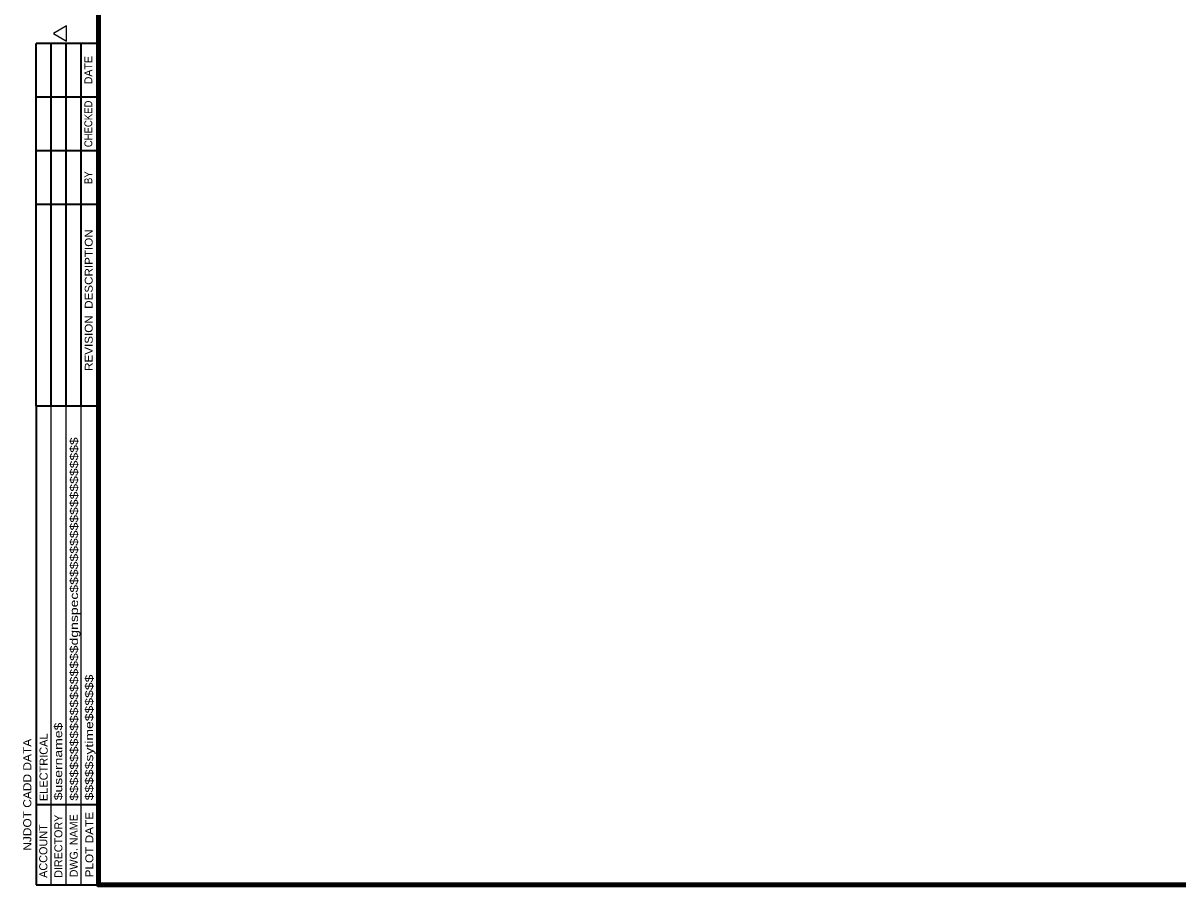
# Model space of a CAD drawing. Extents: x 168203 to 169864, y 223196 to 223870.
# Drawn here: x 169121.7 to 169229.9, y 223368.6 to 223449.3 of the extents above; entities that cross this region are included whole.
import ezdxf
from ezdxf.enums import TextEntityAlignment as Align

# ---------------------------------------------------------------- set-up
doc = ezdxf.new("R2010")
doc.units = 0
doc.header["$LTSCALE"] = 0.3
doc.layers.add('1', color=7, linetype='Continuous', lineweight=13)
doc.layers.add('25', color=7, linetype='Continuous', lineweight=35)

msp = doc.modelspace()

# ---------------------------------------------------------------- linework, layer by layer
at = {"layer": '1', "lineweight": 35}
for p, q in [((169122.946, 223413.5004), (169128.7833, 223413.5004)), ((169122.946, 223413.5004), (169122.946, 223368.6089)), ((169122.946, 223376.145), (169128.7833, 223376.145)), ((169122.946, 223368.6089), (169128.7833, 223368.6089))]:
    msp.add_line(p, q, dxfattribs=at)
at = {"layer": '1', "lineweight": 25}
for p, q in [((169124.3646, 223368.6089), (169124.3646, 223413.5004)), ((169125.7833, 223368.6089), (169125.7833, 223413.5004)), ((169127.1658, 223368.6089), (169127.1658, 223413.5004))]:
    msp.add_line(p, q, dxfattribs=at)
at = {"layer": '1', "lineweight": 158}
msp.add_lwpolyline([(169361.2833, 223368.6089), (169361.2833, 223530.6089), (169128.7833, 223530.6089), (169128.7833, 223368.6089)], close=True, dxfattribs=at)
at = {"layer": '25'}
for p, q in [((169128.7833, 223447.4402), (169122.946, 223447.4402)), ((169122.946, 223413.5004), (169122.946, 223447.4402)), ((169124.3646, 223413.5004), (169124.3646, 223447.4402)), ((169125.7833, 223413.5004), (169125.7833, 223447.4402)), ((169127.1658, 223413.5004), (169127.1658, 223447.4402)), ((169128.7833, 223442.4071), (169122.946, 223442.4071)), ((169128.7833, 223437.3739), (169122.946, 223437.3739)), ((169128.7833, 223432.3408), (169122.946, 223432.3408)), ((169128.5845, 223432.3408), (169127.1658, 223432.3408))]:
    msp.add_line(p, q, dxfattribs=at)
at = {"layer": '25', "lineweight": 25}
msp.add_lwpolyline([(169125.7923, 223449.0667), (169124.5725, 223448.3619), (169125.7923, 223447.6571)], close=True, dxfattribs=at)

# ---------------------------------------------------------------- texts
at = {"layer": '1'}
for s, height, width, p in [('$$$$$$$$$$$$$$$$$$$$dgnspec$$$$$$$$$$$$$$$$$$$$', 0.7526, 1.3, (169126.8767, 223376.4884)), ('$$$$$sytime$$$$$$', 0.7526, 1.3, (169128.2953, 223376.5246)), ('$username$', 0.7526, 1.3, (169125.3947, 223376.5336)), ('NJDOT CADD DATA', 0.759, 1.1, (169122.5032, 223371.8077)), ('PLOT DATE', 0.7499, 1.1, (169128.3134, 223369.3137))]:
    msp.add_text(s, height=height, rotation=90, dxfattribs=dict(at, width=width)).set_placement(p)
for s, height, p in [('ELECTRICAL', 0.768, (169124.0393, 223376.4613)), ('DIRECTORY', 0.75, (169125.4128, 223369.2776)), ('DWG. NAME', 0.75, (169126.8496, 223369.3228)), ('ACCOUNT', 0.7589, (169124.0032, 223369.2685))]:
    msp.add_text(s, height=height, rotation=90, dxfattribs=at).set_placement(p)
at = {"layer": '25'}
msp.add_text('DATE', height=0.741, rotation=90, dxfattribs=at).set_placement((169128.214, 223444.9302), align=Align.CENTER)
for s, width, p in [('CHECKED', 0.9, (169128.214, 223439.8963)), ('BY', 0.9, (169128.214, 223434.8599)), ('REVISION  DESCRIPTION', 1.1, (169128.2502, 223423.3891))]:
    msp.add_text(s, height=0.741, rotation=90, dxfattribs=dict(at, width=width)).set_placement(p, align=Align.CENTER)

doc.saveas('drawing.dxf')
